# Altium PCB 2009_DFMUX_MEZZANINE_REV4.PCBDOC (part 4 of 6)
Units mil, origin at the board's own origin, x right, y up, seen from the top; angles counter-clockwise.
Board outline 4922.86 x 3627.76 mil, 6 copper layers (Top Layer, Internal Plane 1, Mid-Layer 1, Internal Plane 2, Mid-Layer 2, Bottom Layer); 519 components, 606 nets, 2175 pads, 757 vias.
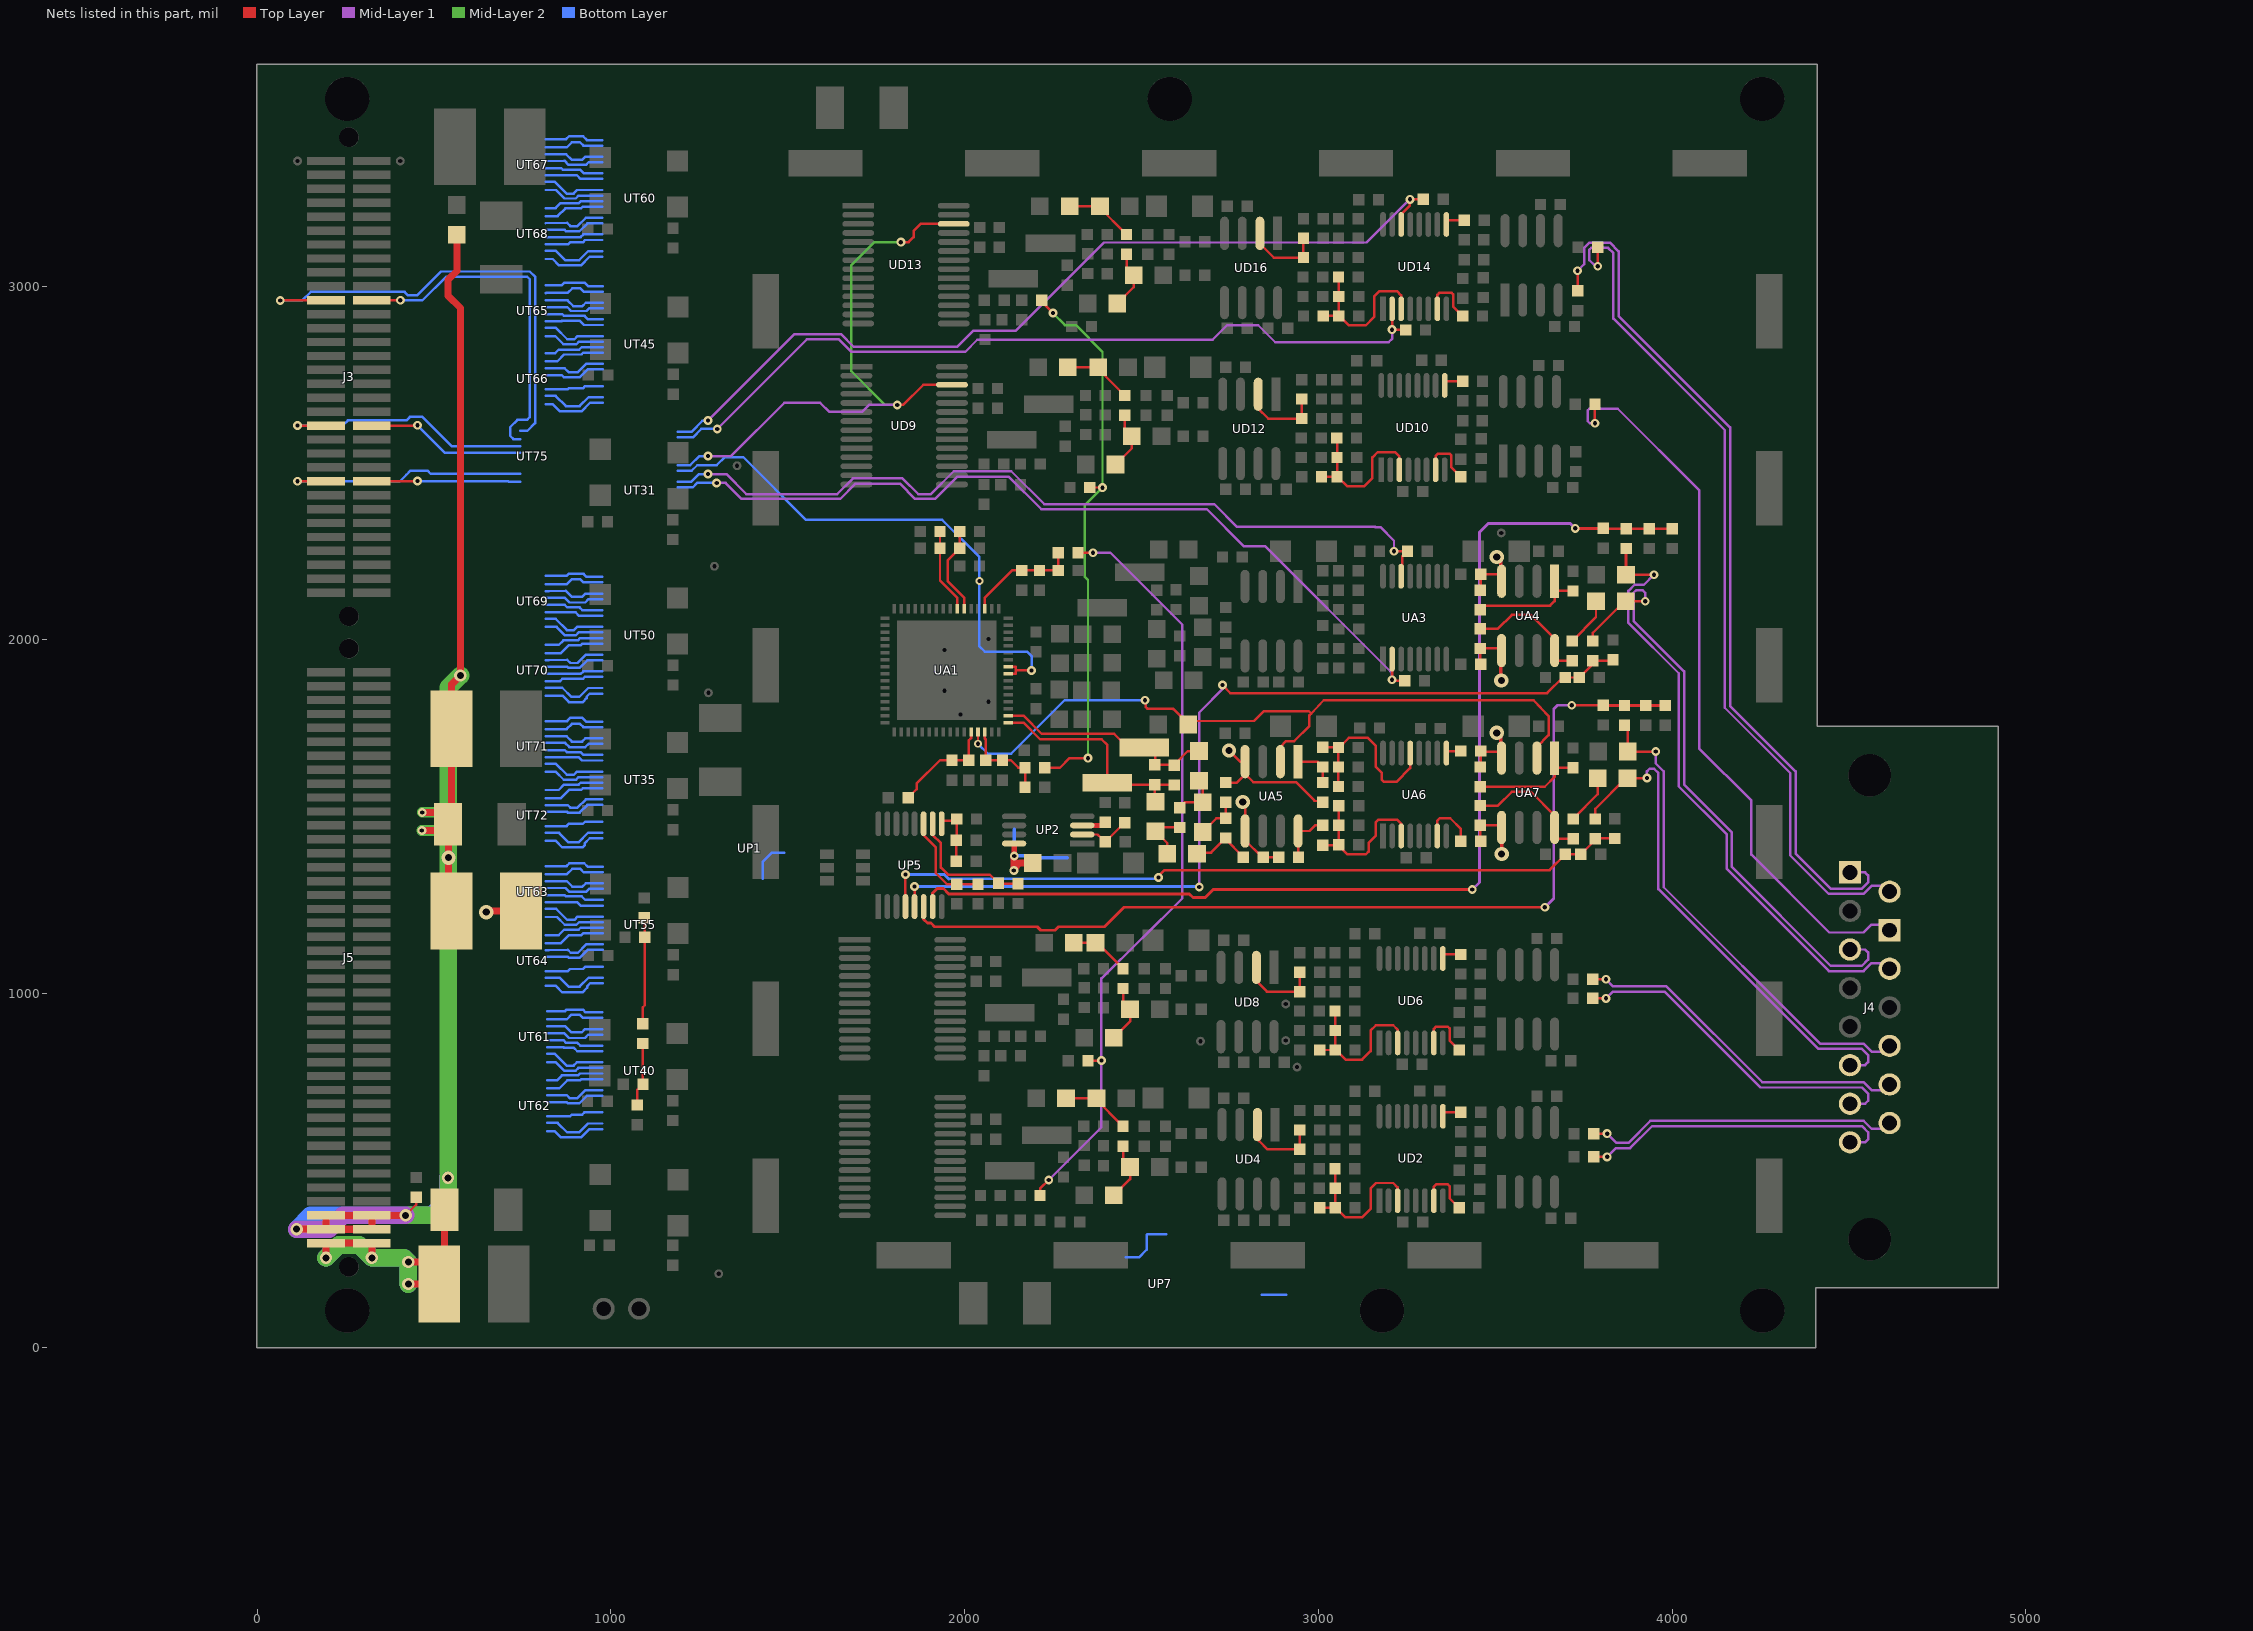
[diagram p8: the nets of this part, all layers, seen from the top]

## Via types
v1: diameter 25, hole 12, Top Layer to Bottom Layer, 692 vias
v2: diameter 40, hole 20, Top Layer to Bottom Layer, 39 vias
v3: diameter 35, hole 20, Top Layer to Bottom Layer, 23 vias
v4: diameter 22, hole 12, Top Layer to Bottom Layer, 3 vias

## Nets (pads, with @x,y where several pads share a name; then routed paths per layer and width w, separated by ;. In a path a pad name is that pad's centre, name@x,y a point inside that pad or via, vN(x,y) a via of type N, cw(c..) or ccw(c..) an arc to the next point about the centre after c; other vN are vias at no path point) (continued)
N196910: RP26.2 RP30.2 UP5.10 | length 370.5
  Top Layer w7: UP5.10@1909.48,1480.05 1909.48,1448.15 1932.63,1425 1932.63,1356.13 1952.63,1336 2071,1336 RP26.2@2095.63,1311.37 2096.63,1310.37 RP30.2@2150.63,1310.37
N197030: RD94.1 RD102.1 UD16.2 | length 223.7
  Top Layer w7: UD16.2@2834.63,3149 2842.63,3141 2842.63,3111.43 2873.63,3080.43 RD102.1@2957.63,3080.43 RD94.1@2957.63,3135.43
N197030_5448: RD64.1 RD72.1 UD12.2 | length 229.8
  Top Layer w7: UD12.2@2829.63,2694 2829.63,2654 2858.2,2625.43 RD72.1@2952.63,2625.43 RD64.1@2952.63,2680.43
N197030_5896: RD34.1 RD42.1 UD8.2 | length 229.2
  Top Layer w7: UD8.2@2824.63,1074 2824.63,1035 2854.2,1005.43 RD42.1@2947.63,1005.43 RD34.1@2947.63,1060.43
N197030_6344: RD4.1 RD12.1 UD4.2 | length 228.3
  Top Layer w7: UD4.2@2827.63,629.43 2832.63,624.43 2832.63,583 2856.2,559.43 RD12.1@2947.63,559.43 RD4.1@2947.63,614.43
N197797: RA5.2 RA6.2 UA1.23 | length 238.1
  Top Layer w7: RA6.2@1930.27,2305.87 RA5.2@1930.27,2258.37 1930.27,2167.37 1978.66,2118.97 UA1.23@1978.66,2087.85
N197910: CA2.1 RA7.2 RA8.2 RA9.1 UA1.19 | length 319.9
  Top Layer w7: UA1.19@2057.4,2087.85 2057.4,2119 2134.27,2195.87 CA2.1@2161.77,2195.87 RA8.2@2211.77,2195.87 RA9.1@2264.27,2195.87 RA7.2@2264.27,2245.87
N197956: RA3.2 RA4.2 UA1.22 | length 251.4
  Top Layer w7: RA4.2@1985.77,2305.87 RA3.2@1985.77,2258.37 1951.77,2224.37 1951.77,2165.87 1998.35,2119.29 UA1.22@1998.35,2087.85
N198124: CA31.1 RA43.2 RA44.1 RA49.2 UA1.62 | length 256
  Top Layer w7: UA1.62@2057.4,1739.43 2057.4,1720.23 2059.27,1718.37 CA31.1@2059.27,1659.37 RA43.2@2106.77,1659.37 2130.77,1659.37 2151.77,1638.37 RA49.2@2170.77,1638.37 RA44.1@2170.77,1583.37
N198251: CA33.2 RA54.1 RA56.2 UA1.60 | length 307.4
  Top Layer w7: RA56.2@1840.27,1553.37 1864.27,1577.37 1864.27,1593.37 1930.27,1659.37 RA54.1@1964.27,1659.37 CA33.2@2011.77,1659.37 2011.77,1715.87 2018.03,1722.13 UA1.60@2018.03,1739.43
N199059: CP4.1 UP1.3 | length 119.3
  Bottom Layer w7: CP4.1@1429.63,1324 1429.63,1373 1454.43,1397.8 UP1.3@1489.63,1397.8
N199942: CP18.1 RP25.1 RP27.1 RP29.2 UP5.5 | length 2623.4
  Top Layer w7: UP5.5@1858.33,1245.8 v1(1858.33,1302.33) ; v1(2728.63,1872) 2751.27,1849 3646.63,1849 3690.63,1893.37 RP25.1@3697.63,1893.37 RP29.2@3737.63,1893.37 3775.63,1931.37 RP27.1@3775.63,1940.37 3829.63,1940.37 CP18.1@3832.63,1943.37
  Mid-Layer 1 w7: v1(2663,1301) 2663,1794 2735,1866 v1(2728.63,1872)
  Bottom Layer w8: v1(1858.33,1302.33) 2661.67,1302.33 v1(2663,1301)
N199948: CP20.1 RP32.1 RP33.2 RP34.2 UP5.4 | length 2158.2
  Top Layer w7: UP5.4@1832.73,1245.8 v1(1832.73,1336.73) ; v1(2548,1328) 2544,1328 2565,1349 3653.27,1349 RP32.1@3697.63,1393.37 RP34.2@3741.63,1393.37 3782.63,1434.37 RP33.2@3782.63,1437.37 3783.63,1438.37 CP20.1@3837.63,1438.37
  Bottom Layer w7: 1955,1324 v1@2544,1324
  Bottom Layer w8: v1(1832.73,1336.73) 1942.27,1336.73 1955,1324 ; v1@2544,1324 v1(2548,1328)
N200349: CA35.2 UA1.61 UA5.2 UA7.2 | length 2139.8
  Top Layer w7: v4(2037.72,1705.87) UA1.61@2037.72,1739.43 ; v1(2510,1829) 2511.63,1829 2511.63,1810.37 2516.57,1805.43 2590,1805.43 2590,1804 2632.6,1761.4 CA35.2@2631.63,1760.43 2641.63,1770.43 2817.63,1770.43 2845.63,1798.43 2972.63,1798.43 2979.63,1791.43 ; UA5.2@2892.63,1655.43 2892.63,1697.43 2908.63,1713.43 2931.63,1713.43 2974.63,1756.43 2974.63,1786.43 2979.63,1791.43 ; UA7.2@3617.63,1665.43 3617.63,1697.43 3650.63,1730.43 3650.63,1784.43 3608.37,1829 3015,1829 2979.63,1791.43
  Mid-Layer 1 w7: v1(2510,1829) 2511.63,1829 v1@2511.63,1825.37
  Bottom Layer w7: v4(2037.72,1705.87) 2065.22,1678.37 2131.77,1678.37 2282.4,1829 v1(2510,1829)
N200703: CA29.2 JA2.2 LA7.1 RA41.1 UA1.1 | length 654.5
  Top Layer w7: UA1.1@2123.35,1766 2166.07,1766 2213.63,1718.43 2387.63,1718.43 2402.63,1703.43 JA2.2@2402.63,1595.43 2407.63,1590.43 RA41.1@2537.63,1590.43 ; LA7.1@2539.63,1542.43 2537.63,1544.43 RA41.1@2537.63,1590.43 ; CA29.2@2592.63,1589.43 2591.63,1590.43 RA41.1@2537.63,1590.43
N205033: CD13.2 LD3.2 LD4.1 | length 166.3
  Top Layer w7: LD3.2@2421.63,429.43 2467.63,475.43 LD4.1@2467.63,509.43 2447.63,529.43 CD13.2@2447.63,568.43
N205033_3007: CD73.2 LD15.2 LD16.1 | length 166.3
  Top Layer w7: LD15.2@2431.63,2950.43 2477.63,2996.43 LD16.1@2477.63,3030.43 2457.63,3050.43 CD73.2@2457.63,3089.43
N205033_5405: CD53.2 LD11.2 LD12.1 | length 166.3
  Top Layer w7: LD11.2@2426.63,2495.43 2472.63,2541.43 LD12.1@2472.63,2575.43 2452.63,2595.43 CD53.2@2452.63,2634.43
N205033_5853: CD33.2 LD7.2 LD8.1 | length 166.3
  Top Layer w7: LD7.2@2421.63,875.43 2467.63,921.43 LD8.1@2467.63,955.43 2447.63,975.43 CD33.2@2447.63,1014.43
N205049: CD13.1 LD1.2 LD2.1 | length 199.1
  Top Layer w7: LD1.2@2286.63,704.43 LD2.1@2367.63,704.43 ; LD2.1@2372.63,704.43 LD2.1@2367.63,704.43 ; CD13.1@2447.63,624.43 LD2.1@2367.63,704.43
N205049_2984: CD73.1 LD13.2 LD14.1 | length 199.1
  Top Layer w7: LD13.2@2296.63,3225.43 LD14.1@2377.63,3225.43 ; LD14.1@2382.63,3225.43 LD14.1@2377.63,3225.43 ; CD73.1@2457.63,3145.43 LD14.1@2377.63,3225.43
N205049_5379: CD53.1 LD9.2 LD10.1 | length 199.1
  Top Layer w7: LD9.2@2291.63,2770.43 LD10.1@2372.63,2770.43 ; LD10.1@2377.63,2770.43 LD10.1@2372.63,2770.43 ; CD53.1@2452.63,2690.43 LD10.1@2372.63,2770.43
N205049_5827: CD33.1 LD5.2 LD6.1 | length 169.8
  Top Layer w7: LD5.2@2308.63,1144 LD6.1@2369.63,1144 2374.63,1144 2447.63,1071 CD33.1@2447.63,1070.43
N205083: RD21.1 RD22.2 RD23.1 RD24.1 UD2.3 | length 458.8
  Top Layer w7: RD22.2@3003.63,394.43 RD23.1@3047.63,394.43 ; RD24.1@3046.63,504.43 3047.63,503.43 RD21.1@3047.63,449.43 RD23.1@3047.63,394.43 ; UD2.3@3223.83,414.43 3223.83,452.23 3211.63,464.43 3162.63,464.43 3147.63,449.43 3147.63,391.43 3123.63,367.43 3076.63,367.43 3049.63,394.43 RD23.1@3047.63,394.43
N205083_3003: RD111.1 RD112.2 RD113.1 RD114.1 UD14.3 | length 458.8
  Top Layer w7: RD112.2@3013.63,2915.43 RD113.1@3057.63,2915.43 ; RD114.1@3056.63,3025.43 3057.63,3024.43 RD111.1@3057.63,2970.43 RD113.1@3057.63,2915.43 ; UD14.3@3233.83,2935.43 3233.83,2973.23 3221.63,2985.43 3172.63,2985.43 3157.63,2970.43 3157.63,2912.43 3133.63,2888.43 3086.63,2888.43 3059.63,2915.43 RD113.1@3057.63,2915.43
N205083_5399: RD81.1 RD82.2 RD83.1 RD84.1 UD10.3 | length 458.8
  Top Layer w7: RD82.2@3008.63,2460.43 RD83.1@3052.63,2460.43 ; RD84.1@3051.63,2570.43 3052.63,2569.43 RD81.1@3052.63,2515.43 RD83.1@3052.63,2460.43 ; UD10.3@3228.83,2480.43 3228.83,2518.23 3216.63,2530.43 3167.63,2530.43 3152.63,2515.43 3152.63,2457.43 3128.63,2433.43 3081.63,2433.43 3054.63,2460.43 RD83.1@3052.63,2460.43
N205083_5847: RD51.1 RD52.2 RD53.1 RD54.1 UD6.3 | length 458.8
  Top Layer w7: RD52.2@3003.63,840.43 RD53.1@3047.63,840.43 ; RD54.1@3046.63,950.43 3047.63,949.43 RD51.1@3047.63,895.43 RD53.1@3047.63,840.43 ; UD6.3@3223.83,860.43 3223.83,898.23 3211.63,910.43 3162.63,910.43 3147.63,895.43 3147.63,837.43 3123.63,813.43 3076.63,813.43 3049.63,840.43 RD53.1@3047.63,840.43
N205093: RD3.1 UD2.9 | length 63.9
  Top Layer w7: UD2.9@3351.72,653.02 3351.72,654.43 3351.63,654.43 3351.63,665.43 3352.63,664.43 RD3.1@3402.63,664.43
N205093_2991: RD93.1 UD14.9 | length 63.9
  Top Layer w7: UD14.9@3361.72,3174.02 3361.72,3175.43 3361.63,3175.43 3361.63,3186.43 3362.63,3185.43 RD93.1@3412.63,3185.43
N205093_5387: RD63.1 UD10.9 | length 63.9
  Top Layer w7: UD10.9@3356.72,2719.02 3356.72,2720.43 3356.63,2720.43 3356.63,2731.43 3357.63,2730.43 RD63.1@3407.63,2730.43
N205093_5835: RD33.1 UD6.9 | length 63.9
  Top Layer w7: UD6.9@3351.72,1099.02 3351.72,1100.43 3351.63,1100.43 3351.63,1111.43 3352.63,1110.43 RD33.1@3402.63,1110.43
N205095: RD27.1 UD2.7 | length 160.9
  Top Layer w7: UD2.7@3326.23,414.43 3326.23,454.03 3332.63,460.43 3365.63,460.43 3370.63,455.43 3370.63,421.43 RD27.1@3397.63,394.43
N205095_2994: RD117.1 UD14.7 | length 160.9
  Top Layer w7: UD14.7@3336.23,2935.43 3336.23,2975.03 3342.63,2981.43 3375.63,2981.43 3380.63,2976.43 3380.63,2942.43 RD117.1@3407.63,2915.43
N205095_5389: RD87.1 UD10.7 | length 160.9
  Top Layer w7: UD10.7@3331.23,2480.43 3331.23,2520.03 3337.63,2526.43 3370.63,2526.43 3375.63,2521.43 3375.63,2487.43 RD87.1@3402.63,2460.43
N205095_5837: RD57.1 UD6.7 | length 160.9
  Top Layer w7: UD6.7@3326.23,860.43 3326.23,900.03 3332.63,906.43 3365.63,906.43 3370.63,901.43 3370.63,867.43 RD57.1@3397.63,840.43
N238970: RA17.2 RA18.1 UA4.4 | length 235.6
  Top Layer w7: RA18.1@3457.63,2140.43 3458.63,2141.43 RA17.2@3458.63,2185.43 3512.63,2185.43 3515,2183.07 3517.63,2180.43 UA4.4@3517.63,2165.43
  Top Layer w10: v2(3504,2234) v2@3515,2223 ; UA4.4@3517.63,2165.43 3515,2168.07 UA4.4@3515,2183.07 ; UA4.4@3515,2183.07 v2@3515,2223 ; UA4.4@3515,2183.07 v2@3515,2223
N238974: RA13.1 RA18.2 UA4.1 | length 328.4
  Top Layer w7: RA18.2@3457.63,2084.43 3469.63,2096.43 3654.63,2096.43 3667.63,2109.43 UA4.1@3667.63,2138 ; UA4.1@3667.63,2165.43 UA4.1@3667.63,2138 ; RA13.1@3719.63,2138 UA4.1@3667.63,2138
N238978: RA28.2 RA29.1 UA4.8 | length 365.2
  Top Layer w7: RA28.2@3457.63,2031.43 3507.63,2031.43 3546.63,2070.43 3600.63,2070.43 3667.63,2003.43 UA4.8@3667.63,1969.43 3667.63,1943.37 3670.57,1940.43 RA29.1@3717.63,1940.43
N238986: RA27.2 RA28.1 UA4.5 | length 193.5
  Top Layer w7: RA27.2@3458.63,1930.43 3457.63,1931.43 RA28.1@3457.63,1975.43 3511.63,1975.43 UA4.5@3517.63,1969.43
  Top Layer w10: v2(3517,1885) 3516,1886 3516,1968 3517.43,1969.43 UA4.5@3517.63,1969.43
N244377: RP28.2 RP31.2 UP5.11 | length 286.1
  Top Layer w7: UP5.11@1883.88,1480.05 1883.88,1448.12 1918.63,1413.37 1918.63,1340 1949.27,1309.37 RP31.2@1977.63,1309.37 RP28.2@2037.63,1309.37
N245845: CA47.1 RA29.2 | length 140.3
  Top Layer w7: RA29.2@3717.63,1996.43 3717.63,1997 3784.63,2064 CA47.1@3784.63,2109
N247609: RP21.2 RP22.2 RP23.1 UP5.9 | length 170.6
  Top Layer w7: UP5.9@1935.07,1480.05 1935.07,1484.62 1939.85,1489 1973.63,1489 1977.63,1493 RP23.1@1977.63,1493.37 1977.63,1434.37 RP22.2@1976.63,1433.37 RP21.2@1976.63,1374
N247828: RA45.1 RA47.2 RA48.1 RA50.1 UA6.3 | length 460.9
  Top Layer w7: RA47.2@3012.63,1419.43 3056.63,1419.43 RA50.1@3057.63,1420.43 ; RA48.1@3057.63,1530.43 RA45.1@3057.63,1475.43 RA50.1@3057.63,1420.43 ; UA6.3@3233.83,1445.43 3233.83,1480.23 3222.63,1491.43 3169.63,1491.43 3161.63,1483.43 3161.63,1445.43 3141.63,1425.43 3141.63,1401.43 3133.63,1393.43 3081.63,1393.43 3057.63,1417.43 RA50.1@3057.63,1420.43
N247840: RA34.1 UA6.9 | length 43.2
  Top Layer w7: UA6.9@3361.77,1679.68 3367.52,1685.43 RA34.1@3402.63,1685.43
N247844: RA51.1 UA6.7 | length 160.1
  Top Layer w7: UA6.7@3336.23,1445.43 3336.23,1489.03 3342.63,1495.43 3372.63,1495.43 3402.63,1465.43 RA51.1@3402.63,1430.43
N247852: RA33.2 RA37.2 RA38.2 RA39.2 UA6.13 | length 524.2
  Top Layer w7: RA33.2@3012.63,1696.43 3055.63,1696.43 RA37.2@3056.63,1695.43 RA37.2@3057.63,1694.43 ; RA39.2@3056.63,1585.43 RA38.2@3056.63,1640.43 3056.63,1693.43 RA37.2@3057.63,1694.43 ; UA6.13@3259.4,1679.68 3259.4,1637.2 3220.63,1598.43 3185.63,1598.43 3178.63,1605.43 3178.63,1624.43 3162.63,1640.43 3162.63,1699.43 3139.63,1722.43 3085.63,1722.43 RA37.2@3057.63,1694.43
N247880: RA32.1 RA40.2 UA5.4 | length 410.8
  Top Layer w7: RA40.2@2737.63,1596.43 2769.63,1596.43 2792.63,1619.43 UA5.4@2792.63,1620.43 ; v2(2747,1687) 2778.57,1655.43 UA5.4@2792.63,1655.43 UA5.4@2792.63,1620.43 ; RA32.1@3012.63,1540.43 2988.63,1545.43 2936.63,1597.43 2815.63,1597.43 UA5.4@2792.63,1620.43
N247884: RA32.2 RA33.1 UA5.1 | length 120.2
  Top Layer w7: UA5.1@2942.63,1655.43 2997.63,1655.43 RA33.1@3012.63,1640.43 RA32.2@3012.63,1596.43
N247888: RA46.2 RA47.1 UA5.8 | length 151
  Top Layer w7: RA46.2@2943.63,1385.43 2942.63,1386.43 UA5.8@2942.63,1459.43 2974.63,1459.43 2990.63,1475.43 RA47.1@3012.63,1475.43
N247896: RA42.2 RA46.1 UA5.5 | length 225.2
  Top Layer w7: v2(2786,1541) 2792.63,1534.37 UA5.5@2792.63,1459.43 2792.63,1433.43 2840.63,1385.43 RA42.2@2843.63,1385.43 RA46.1@2887.63,1385.43
N247928: CA29.1 JA2.1 LA5.1 RA41.2 UA1.2 | length 635.3
  Top Layer w7: UA1.2@2123.35,1785.69 2166.37,1785.7 2217.63,1734.43 2422.63,1734.43 2461.63,1695.43 JA2.1@2507.63,1695.43 2521.63,1695.43 2538.63,1678.43 2538.63,1647.43 RA41.2@2537.63,1646.43 2591.63,1646.43 CA29.1@2592.63,1645.43 2592.63,1647.43 2630.63,1685.43 LA5.1@2662.63,1685.43
N247964: RA34.2 RA35.1 UA7.4 | length 196.3
  Top Layer w7: RA35.1@3457.63,1640.43 3458.63,1641.43 RA34.2@3458.63,1685.43 3460.07,1684 3510,1684 3515,1679 3517.63,1676.37 UA7.4@3517.63,1665.43
  Top Layer w10: v2(3504,1737) 3515,1726 3515,1679 3515,1668.07 UA7.4@3517.63,1665.43
N247968: RA35.2 RA36.1 UA7.1 | length 327.8
  Top Layer w7: RA35.2@3457.63,1584.43 3639.63,1584.43 3667.63,1612.43 3667.63,1635 UA7.1@3670.63,1638 ; UA7.1@3667.63,1665.43 3667.63,1638 UA7.1@3670.63,1638 ; RA36.1@3719.63,1638 UA7.1@3670.63,1638
N247972: RA52.2 RA53.1 UA7.8 | length 365.9
  Top Layer w7: RA52.2@3457.63,1531.43 3507.63,1531.43 3546.63,1570.43 3600.63,1570.43 3667.63,1503.43 UA7.8@3667.63,1469.43 3667.63,1449.37 3679.57,1437.43 RA53.1@3720.63,1437.43
N247980: RA51.2 RA52.1 UA7.5 | length 183.5
  Top Layer w7: RA51.2@3458.63,1430.43 3457.63,1431.43 RA52.1@3457.63,1475.43 3511.63,1475.43 UA7.5@3517.63,1469.43
  Top Layer w10: UA7.5@3517.63,1469.43 3518,1469.07 v2(3518,1394)
N248164: CA30.1 LA6.2 RA40.1 | length 126.2
  Top Layer w7: LA6.2@2672.63,1456.43 2711.63,1495.43 CA30.1@2737.63,1495.43 RA40.1@2737.63,1540.43
N248168: CA30.2 LA8.2 RA42.1 | length 173.9
  Top Layer w7: LA8.2@2656.63,1395.43 2659.63,1398.43 2696.63,1398.43 CA30.2@2737.63,1439.43 2737.63,1436.43 2787.63,1386.43 RA42.1@2787.63,1385.43
N248172: CA28.1 LA5.2 LA6.1 | length 136.4
  Top Layer w7: CA28.1@2607.63,1525.43 2622.63,1540.43 LA6.1@2672.63,1540.43 2672.63,1591.43 LA5.2@2662.63,1601.43
N248196: CA28.2 LA7.2 LA8.1 | length 149.2
  Top Layer w7: LA8.1@2572.63,1395.43 2572.63,1425.43 LA7.2@2539.63,1458.43 2550.63,1469.43 CA28.2@2607.63,1469.43
N248744: CA49.1 RA53.2 | length 144.1
  Top Layer w7: RA53.2@3720.63,1493.43 3720.63,1495 3789.63,1564 CA49.1@3789.63,1609
N536527: CA47.2 J4.3 RP27.2 | length 1743.7
  Top Layer w7: RP27.2@3775.63,1996.37 3775.63,2020 3864.63,2109 CA47.2@3868.63,2109 v1(3923.63,2109)
  Mid-Layer 1 w7: v1(3923.63,2109) 3923.63,2132.93 3916.13,2140.43 3898.63,2140.43 3891.13,2132.93 3891.13,2052.93 4033.63,1910.43 4033.63,1590.43 4168.63,1455.43 4168.63,1357.93 4448,1078.57 4536.13,1078.57 4553.63,1096.07 4553.63,1116.07 4545.2,1124.5 J4.3@4502.5,1124.5
N536537: CA46.1 J4.11 RP56.2 | length 1741.4
  Top Layer w7: CA46.1@3869.63,2184 v1(3948.63,2184)
  Top Layer w8: CA46.1@3869.63,2184 3869.63,2257.63 RP56.2@3870,2258
  Mid-Layer 1 w7: v1(3948.63,2184) 3920.07,2155.43 3893.63,2155.43 3876.13,2137.93 3876.13,2047.93 4018.63,1905.43 4018.63,1585.43 4153.63,1450.43 4153.63,1352.93 4443,1063.57 4541.13,1063.57 4563.63,1086.07 4598.43,1086.07 J4.11@4614.5,1070
N536553: CA48.1 J4.13 RP59.2 | length 1387.3
  Top Layer w7: RP59.2@3865,1758 3874.63,1748.37 CA48.1@3874.63,1684 v1(3953.63,1684)
  Mid-Layer 1 w7: v1(3953.63,1684) 3953.63,1650.43 3976.13,1627.93 3976.13,1300.43 4418.13,858.43 4541.13,858.43 4563.63,835.93 4598.43,835.93 J4.13@4614.5,852
N536575: CA49.2 J4.6 RP33.1 | length 1455.6
  Top Layer w7: RP33.1@3782.57,1493.43 RP33.1@3782.63,1493.37 3782.63,1522 CA49.2@3869.63,1609 ; CA49.2@3873.63,1609 v1(3928.63,1609)
  Mid-Layer 1 w7: v1(3928.63,1609) 3928.63,1627.93 3936.13,1635.43 3948.63,1635.43 3961.13,1622.93 3961.13,1295.43 4413.13,843.43 4536.13,843.43 4553.63,825.93 4553.63,805.93 4545.2,797.5 J4.6@4502.5,797.5
N536618: J4.14 RD43.2 | length 975.4
  Top Layer w7: RD43.2@3775.63,1040.37 v1(3813.13,1040.37)
  Mid-Layer 1 w7: v1(3813.13,1040.37) 3833.07,1020.43 3983.63,1020.43 4254.63,749.43 4541.13,749.43 4563.63,726.93 4598.43,726.93 J4.14@4614.5,743
N536666: J4.7 RD48.2 | length 980
  Top Layer w7: RD48.2@3775.63,986.37 v1(3813.13,986.37)
  Mid-Layer 1 w7: v1(3813.13,986.37) 3832.2,1005.43 3978.63,1005.43 4249.63,734.43 4536.13,734.43 4553.63,716.93 4553.63,696.93 4545.2,688.5 J4.7@4502.5,688.5
N538961: J4.15 RD13.2 | length 888.5
  Top Layer w7: RD13.2@3778.63,604 v1(3816.13,604)
  Mid-Layer 1 w7: v1(3816.13,604) 3842.2,577.93 3876.13,577.93 3938.63,640.43 4541.13,640.43 4563.63,617.93 4598.43,617.93 J4.15@4614.5,634
N539025: J4.8 RD18.2 | length 892.9
  Top Layer w7: RD18.2@3778.63,538.37 v1(3816.13,538.37)
  Mid-Layer 1 w7: v1(3816.13,538.37) 3840.7,562.93 3881.13,562.93 3943.63,625.43 4536.13,625.43 4553.63,607.93 4553.63,587.93 4545.2,579.5 J4.8@4502.5,579.5
N539569: J4.10 RD73.2 | length 2108.5
  Top Layer w7: v1(3781.63,2612) RD73.2@3781.63,2666
  Mid-Layer 1 w7: v1(3781.63,2612) 3767.07,2612 3761.13,2617.93 3761.13,2647.93 3766.13,2652.93 3846.13,2652.93 4076.13,2422.93 4076.13,1692.93 4223.63,1545.43 4223.63,1392.93 4444,1172.57 4541.13,1172.57 4563.63,1195.07 4598.43,1195.07 J4.10@4614.5,1179
N539716: J4.1 RD108.2 | length 2480.7
  Top Layer w7: RD108.2@3732.63,2986.43 v1(3732.63,3042.93)
  Mid-Layer 1 w7: v1(3732.63,3042.93) 3751.13,3061.43 3751.13,3107.93 3766.13,3122.93 3823.63,3122.93 3848.63,3097.93 3848.63,2915.43 4163.63,2600.43 4163.63,1812.93 4348.63,1627.93 4348.63,1395.43 4447.5,1296.57 4536.13,1296.57 4553.63,1314.07 4553.63,1334.07 4545.2,1342.5 J4.1@4502.5,1342.5
N539798: J4.9 RD103.2 | length 2441.8
  Top Layer w7: v1(3789.63,3056) RD103.2@3789.63,3110
  Mid-Layer 1 w7: v1(3789.63,3056) 3783.07,3056 3766.13,3072.93 3766.13,3102.93 3771.13,3107.93 3818.63,3107.93 3833.63,3092.93 3833.63,2907.93 4148.63,2592.93 4148.63,1807.93 4333.63,1622.93 4333.63,1390.43 4442.5,1281.57 4541.13,1281.57 4563.63,1304.07 4598.43,1304.07 J4.9@4614.5,1288
N562193: RA30.2 UA3.2 UT31.12 | length 2470.3
  Top Layer w7: UA3.2@3208.23,1945.43 3206.63,1943.83 3206.63,1934.43 3208.63,1932.43 3208.63,1894 3199.63,1885 3207.63,1885 v1(3207.63,1887) 3210.63,1884 RA30.2@3243.63,1884
  Mid-Layer 1 w7: v1(1299,2443.37) 1324.27,2443.37 1369.63,2398 1648.36,2398 1691.77,2441.41 1816.77,2441.41 1860.18,2398 1915.86,2398 1979.27,2461.41 2124.27,2461.41 2216.68,2369 2685,2369 2790,2264 2850,2264 3203,1911 3207.63,1911 v1(3207.63,1887)
  Bottom Layer w7: UT31.12@1188.63,2430.67 1231.5,2430.67 1243.8,2443.37 v1(1299,2443.37)
N562649: RA10.2 UA3.14 UT31.11 | length 2348
  Top Layer w7: v1(3213.63,2250.43) RA10.2@3251.63,2250.43 3236.63,2235.43 3236.63,2182.5 UA3.14@3233.82,2179.68
  Mid-Layer 1 w7: v1(1274.27,2468.37) 1326.27,2468.37 1382.63,2412 1639.86,2412 1684.27,2456.41 1824.27,2456.41 1868.68,2412 1904.86,2412 1969.27,2476.41 2131.77,2476.41 2225.18,2383 2706,2383 2770,2319 3160,2319 3160.37,2318.63 3175,2318.63 3213.63,2280 v1(3213.63,2250.43)
  Bottom Layer w7: UT31.11@1188.63,2446.37 1227,2446.37 1249,2468.37 v1(1274.27,2468.37)
N563114: RA1.1 UA1.8 UA1.9 UT31.9 | length 1546
  Top Layer w7: UA1.8@2122.63,1903.9 UA1.8@2123.35,1903.9 ; UA1.9@2122.63,1923.6 UA1.9@2123.35,1923.6 ; UA1.8@2123.35,1903.8 2144.27,1903.8 2144.27,1923.48 UA1.9@2123.35,1923.48 ; 2144.27,1913.37 v1(2189.27,1913.37)
  Bottom Layer w7: UT31.9@1188.63,2477.77 1228.4,2477.77 1244,2493.37 1299,2493.37 1322.04,2516.41 1374.27,2516.41 1551.77,2338.91 1936.77,2338.91 2041.77,2233.91 RA1.1@2041.77,2208.37 v4(2041.77,2165.87) 2041.77,1981.41 2056.77,1966.41 2176.77,1966.41 2189.27,1953.91 v1(2189.27,1913.37)
N563431: UD9.26 UD13.26 UT31.8 | length 1708.6
  Top Layer w7: v1(1809.63,2664) 1826.27,2664 1882.9,2720.63 UD9.26@1964.03,2720.63 ; v1(1819.63,3124) 1841.63,3124 1855.63,3138 1855.63,3156 1875.27,3175.63 UD13.26@1969.03,3175.63
  Mid-Layer 1 w7: v1(1274.27,2519.37) 1340,2519.37 1490.63,2670 1591.63,2670 1617.63,2644 1709.63,2644 1729.63,2664 v1(1809.63,2664)
  Mid-Layer 2 w7: v1(1809.63,2664) 1774.63,2664 1679.63,2759 1679.63,3059 1744.63,3124 v1(1819.63,3124)
  Bottom Layer w7: UT31.8@1188.63,2493.47 1224.1,2493.47 1250,2519.37 v1(1274.27,2519.37)
N564745: RD119.2 UD14.2 UT31.3 | length 2328.2
  Top Layer w7: UD14.2@3208.23,2935.43 v1(3208.23,2876.6) 3246.47,2876.6 3246.63,2876.43 RD119.2@3246.63,2875.43
  Mid-Layer 1 w7: v1(1300.63,2596) 1553.63,2849 1644.63,2849 1679.63,2814 2001.63,2814 2035.63,2848 2701,2848 2742,2889 2830,2889 2878,2841 3198.63,2841 3208.23,2850.6 v1(3208.23,2876.6)
  Bottom Layer w7: UT31.3@1188.63,2571.97 1231.88,2571.97 1255.52,2596 v1(1300.63,2596)
N565087: RD91.2 UD14.14 UT31.2 | length 2496
  Top Layer w7: UD14.14@3233.8,3174.02 3231.63,3176.18 3231.63,3200.43 3258.63,3227.43 v1@3258.63,3245.43 ; v1(3258.63,3245) v1@3258.63,3245.43 ; RD91.2@3296.63,3245.43 v1@3258.63,3245.43
  Mid-Layer 1 w7: v1(1274.63,2620) 1518.63,2864 1650.63,2864 1686.63,2828 1978.63,2828 2023.63,2873 2144,2873 2394,3123 3135.63,3123 3257.63,3245 v1(3258.63,3245)
  Bottom Layer w7: UT31.2@1188.63,2587.67 1227.3,2587.67 1258.63,2619 1275.63,2619 v1(1274.63,2620)
N565612: J3.48 UT75.9 | length 420.9
  Top Layer w7: J3.48@324.55,2448 452.87,2448 v1(453.63,2448.77)
  Bottom Layer w7: v1(453.63,2448.77) 709.63,2448.77 712.03,2446.37 UT75.9@744.13,2446.37
N566158: J3.47 UT75.10 | length 807.7
  Top Layer w7: v1@113.63,2447 115,2448 194.63,2448 v1(114.33,2448)
  Bottom Layer w7: v1(114.33,2448) 403.55,2448 422.05,2466.37 ; 422.07,2466.37 433.93,2478.37 481.63,2478.37 490.63,2469.37 UT75.10@744.13,2469.37
N570816: CP9.1 CP23.1 CP24.1 LP2.2 RP11.1 UP2.8 | length 643.9
  Top Layer w7: v2(647.63,1230) v2@651,1233.37 ; UP2.8@2139.73,1424 2139.73,1388.1 2140.63,1389 v1(2140,1389)
  Top Layer w10: UP2.8@2139.73,1424 UP2.8@2140,1423.73
  Top Layer w15: v1@2140,1389 UP2.8@2140,1423.73
  Top Layer w20: v2@651,1233.37 LP2.2@746.3,1233.37 ; v1(2140,1389) 2140,1354 2155,1369 RP11.1@2192.63,1369
  Bottom Layer w7: 2200,1389 CP9.1@2205,1384
  Bottom Layer w10: 2200,1389 v1(2140,1389) ; CP9.1@2205,1384 CP24.1@2290,1384 ; v1(2140,1389) CP23.1@2140,1464 ; v1(2140,1389) CP23.1@2140,1464 ; v1(2140,1389) CP23.1@2140,1464
  other v1: 2139,1348
N570824: CP8.1 UP2.3 | length 68.6
  Top Layer w7: CP8.1@2388.83,1475.2 CP8.1@2397.63,1484
  Top Layer w15: UP2.3@2332.63,1475.2 CP8.1@2388.83,1475.2
N570828: RP9.2 RP10.1 UP2.2 | length 154.5
  Top Layer w7: UP2.2@2332.63,1449.6 2376.03,1449.6 2386.63,1439 2397.63,1439 RP10.1@2403.13,1433.5 ; RP10.1@2397.63,1429 2398.63,1429 RP10.1@2403.13,1433.5 ; RP9.2@2452.63,1483 RP10.1@2403.13,1433.5
N570972: J3.40 UT75.13 | length 452.2
  Top Layer w7: J3.40@324.55,2605.47 452.87,2605.47 v1(453.63,2606.23)
  Bottom Layer w7: v1(453.63,2606.23) 453.77,2606.23 531.63,2528.37 UT75.13@744.13,2528.37
N571170: J3.39 UT75.14 | length 754.5
  Top Layer w7: v1(114.33,2605.47) J3.39@194.63,2605.47
  Bottom Layer w7: v1(114.33,2605.47) 241.73,2605.47 256.63,2620.37 422.03,2620.37 431.63,2629.97 467.03,2629.97 549.63,2547.37 UT75.14@744.13,2547.37
N582215: J3.22 UT75.15 | length 989.9
  Top Layer w7: J3.22@324.55,2959.77 v1(404.85,2959.77)
  Bottom Layer w7: v1(404.85,2959.77) 467.4,2959.77 534,3026 763.63,3026 770.63,3019.37 770.63,2629.37 762.63,2621.37 735.63,2621.37 715.63,2601.37 715.63,2576.37 724.63,2567.37 UT75.15@744.13,2567.37
N582703: J3.21 UT75.16 | length 1363.4
  Top Layer w7: v1@64.23,2959.77 v1@66.32,2959.77 ; v1(65.55,2959) v1@66.32,2959.77 ; J3.21@194.63,2959.77 v1@66.32,2959.77
  Bottom Layer w7: v1(65.55,2959) 127.27,2959 151.7,2983.43 416.63,2983.43 425.63,2974.43 453.07,2974.43 520,3041 770.63,3041 785.63,3026.37 785.63,2612.37 763.63,2590.37 UT75.16@744.13,2590.37
N609644: CP1.2 RP1.2 RP2.1 | length 181
  Top Layer w7: RP1.2@1074.63,685 1074.63,728 CP1.2@1090.63,744 1090.63,858 RP2.1@1089.63,859
N609835: CP2.2 RP2.2 RP3.1 | length 301.9
  Top Layer w7: RP2.2@1089.63,915 1089.63,961 1095.63,967 CP2.2@1095.63,1159 1095.63,1213 RP3.1@1094.63,1214
N611462: RA7.1 RD20.2 RD60.2 | length 2197.6
  Top Layer w7: RD20.2@2213.13,429 2213.13,448.5 v1(2237.63,473) ; RA7.1@2320.27,2245.87 v1(2362.77,2245.87) ; RD60.2@2348.63,810.43 v1(2386.57,810.43)
  Mid-Layer 1 w7: v1(2237.63,473) 2386.57,621.93 v1(2386.57,810.43) 2386.57,1042.93 2615,1269 2615,2042.64 2411.77,2245.87 v1(2362.77,2245.87)
N612269: RA49.1 RD90.2 RD110.2 | length 1578.9
  Top Layer w7: RD110.2@2217.63,2960 2217.63,2956 v1(2249.63,2924) ; RA49.1@2226.77,1638.37 2269.27,1638.37 2296.27,1665.37 v1(2348.63,1665.37) ; RD90.2@2353.63,2430.43 2390.07,2430.43 v1(2389.63,2430)
  Mid-Layer 2 w7: v1(2249.63,2924) 2249.57,2923.93 2249.57,2923.07 2283.2,2889.43 2314.2,2889.43 2389.63,2814 v1(2389.63,2430) 2339.27,2379.64 2339.27,2178.37 2348.63,2169 v1(2348.63,1665.37)
N617296: CP5.1 J5.79 J5.80 J5.81 J5.82 LP1.1 LP2.1 RP4.2 RP13.2 | length 5781.1
  Top Layer w7: J5.80@324.55,373.07 324.62,373 v3@416.63,373 ; v3@416.7,373.07 v3@416.63,373 ; RP4.2@449.63,424 449.63,403 v3(419.63,373) v3@416.63,373 ; CP5.1@523.63,1444.73 539.63,1460.73 CP5.1@539.63,1478.37 ; CP5.1@523.63,1512 539.63,1496 CP5.1@539.63,1478.37 ; LP2.1@540.63,1242.37 LP2.1@549.63,1233.37 ; CP5.1@540.63,1477.37 CP5.1@539.63,1478.37 ; LP1.1@547.63,1796 549.63,1798 LP1.1@549.63,1748.37 ; CP5.1@549.63,1488 540,1478.37 CP5.1@539.63,1478.37 ; CP5.1@539.63,1478 CP5.1@539.63,1478.37 ; CP5.1@539.63,1478 522.63,1461 CP5.1@539.63,1478
  Top Layer w20: v3(111.63,334) 194.33,334 J5.81@194.63,333.7 ; v1(466.63,1512) CP5.1@523.63,1512 ; LP2.1@540.63,1242.37 v2(540.63,1384) CP5.1@540.63,1477.37 ; CP5.1@549.63,1488 LP1.1@549.63,1748.37 550,1748.73 550,1798.37 550,1874.37 ; RP13.2@564.63,3145 564.63,3042.13 540,3017.5 540,2972.5 574.63,2937.87 v3(574.63,1899) ; J5.81@194.63,333.7 J5.79@194.63,373.07 ; J5.81@194.63,333.7 J5.82@324.55,333.7 J5.80@324.55,373.07 ; J5.81@194.63,333.7 J5.79@194.63,373.07 ; J5.79@194.63,373.07 J5.80@324.55,373.07 ; J5.80@324.55,373.07 416.7,373.07 J5.80@324.55,373.07 ; 550,1874.37 v3(574.63,1899) ; 550,1874.37 v3(574.63,1899) ; v1(465.63,1461) 522.63,1461 v1(465.63,1461)
  Mid-Layer 1 w50: v3(111.63,334) 204,334 243,373 v3(419.63,373)
  Mid-Layer 2 w30: v1(465.63,1461) 539.13,1461 ; v1(466.63,1512) 538.63,1512
  Mid-Layer 2 w50: v3(419.63,373) 508,373 540.63,405.63 v2(540.63,1384) 540.63,1865 v3(574.63,1899)
  Bottom Layer w50: v3(111.63,334) 150.63,373 v3(419.63,373) 493.63,373 539.63,419 v3(539.63,479)
N617312: CP17.2 J5.83 J5.84 LP4.1 | length 1427.3
  Top Layer w7: LP4.1@513.63,241 LP4.1@514.63,240 ; LP4.1@529.63,194 LP4.1@514.63,179 ; LP4.1@514.63,179 LP4.1@514.63,240 ; LP4.1@514.63,179 LP4.1@514.63,240
  Top Layer w20: v3(194.63,252.92) J5.83@194.63,294.33 J5.84@324.55,294.33 ; v3(427.63,179) LP4.1@514.63,179 ; v3(427.63,241) LP4.1@513.63,241 ; LP4.1@529.63,194 CP17.2@529.63,389 ; J5.84@324.55,294.33 v3(324.55,252.92) J5.84@324.55,294.33
  Mid-Layer 2 w50: v3(194.63,252.92) 230.72,289 288.47,289 v3(324.55,252.92) 415.72,252.92 v3(427.63,241) v3(427.63,179)
  Bottom Layer w50: v3(194.63,252.92) 231.72,290 287.47,290 v3(324.55,252.92) 415.72,252.92 v3(427.63,241) v3(427.63,179)
N714404: DP4.1 RP19.1 | length 70
  Bottom Layer w7: DP4.1@2839.63,149 RP19.1@2909.63,149
N717936: RP20.1 RP24.2 UP7.4 | length 166.5
  Bottom Layer w7: UP7.4@2454.63,254 2492.63,254 2514.63,276 RP20.1@2514.63,318 2515.63,319 RP24.2@2569.63,319
N794655: CP45.1 RP54.1 RP55.2 RP56.1 UP5.7 | length 3168.1
  Top Layer w8: UP5.7@1909.53,1245.8 1909.53,1283.53 1922.5,1296.5 1940,1296.5 1955,1281.5 2635,1281.5 2645,1271.5 2680,1271.5 2702.5,1294 v1(3435,1294) ; v1(3726,2315) RP55.2@3805,2315 3806,2314 RP56.1@3870,2314 RP54.1@3935,2314 CP45.1@4000,2314
  Mid-Layer 1 w8: v1(3435,1294) 3455,1314 3455,2304 3480,2329 3712,2329 v1(3726,2315)
N795104: CP46.1 RP57.1 RP58.2 RP59.1 UP5.6 | length 2721.9
  Top Layer w8: UP5.6@1883.93,1245.8 1883.93,1210.07 1895,1199 1905,1199 1915,1189 2205,1189 2215,1179 2255,1179 2265,1189 2395,1189 2450,1244 v1(3640,1244) ; v1(3716,1815) RP58.2@3805,1815 3806,1814 RP59.1@3865,1814 RP57.1@3925,1814 CP46.1@3980,1814
  Mid-Layer 1 w8: v1(3640,1244) 3665,1269 3665,1804 3676,1815 v1(3716,1815)
N839929: UT50.29 UT70.6 | length 165.9
  Bottom Layer w7: UT70.6@815.13,1883.37 856.63,1883.37 862.63,1889.37 920.83,1889.37 926.13,1895.07 UT50.29@976.03,1895.07
N839929_9383: UT60.29 UT68.6 | length 165.7
  Bottom Layer w7: UT68.6@815.13,3118.37 879.63,3118.37 884.63,3123.37 920.63,3123.37 927.33,3130.07 UT60.29@976.03,3130.07
N839929_10469: UT45.29 UT66.6 | length 165.5
  Bottom Layer w7: UT66.6@815.13,2708.37 878.63,2708.37 880.63,2710.37 920.63,2710.37 927.33,2717.07 UT45.29@977.03,2717.07
N839929_10665: UT55.29 UT64.6 | length 167.2
  Bottom Layer w7: UT64.6@815.13,1063.37 878.63,1063.37 884.63,1069.37 921.63,1069.37 928.33,1076.07 UT55.29@977.03,1076.07
N839929_10861: UT40.29 UT62.6 | length 159.3
  Bottom Layer w7: UT62.6@820.13,653.37 884.63,653.37 888.63,657.37 918.63,657.37 925.33,664.07 UT40.29@975.03,664.07
N839929_11253: UT35.29 UT72.6 | length 166.1
  Bottom Layer w7: UT72.6@815.13,1473.37 874.63,1473.37 880.63,1479.37 920.63,1479.37 927.63,1486.07 UT35.29@976.03,1486.07
N839997: UT50.27 UT70.7 | length 182.1
  Bottom Layer w7: UT70.7@815.13,1864.37 862.63,1864.37 888.63,1838.37 910.63,1838.37 935.93,1863.67 UT50.27@976.03,1863.67
N839997_9355: UT60.27 UT68.7 | length 182.1
  Bottom Layer w7: UT68.7@815.13,3099.37 844.63,3099.37 870.63,3073.37 910.63,3073.37 935.93,3098.67 UT60.27@976.03,3098.67
N839997_10465: UT45.27 UT66.7 | length 184.4
  Bottom Layer w7: UT66.7@815.13,2689.37 843.63,2689.37 872.63,2660.37 911.63,2660.37 936.93,2685.67 UT45.27@977.03,2685.67
N839997_10661: UT55.27 UT64.7 | length 182.7
  Bottom Layer w7: UT64.7@815.13,1044.37 855.63,1044.37 880.63,1019.37 911.63,1019.37 936.93,1044.67 UT55.27@977.03,1044.67
N839997_10857: UT40.27 UT62.7 | length 176.6
  Bottom Layer w7: UT62.7@820.13,634.37 849.63,634.37 876.63,607.37 909.63,607.37 934.93,632.67 UT40.27@975.03,632.67
N839997_11249: UT35.27 UT72.7 | length 183.4
  Bottom Layer w7: UT72.7@815.13,1454.37 853.63,1454.37 880.63,1427.37 908.63,1427.37 935.93,1454.67 UT35.27@976.03,1454.67
N840117: UT50.26 UT70.8 | length 180.6
  Bottom Layer w7: UT70.8@815.13,1841.37 864.27,1841.37 881.27,1824 920.63,1824 931.63,1835.37 931.63,1839.37 940.23,1847.97 UT50.26@976.03,1847.97
N840117_9365: UT60.26 UT68.8 | length 178.5
  Bottom Layer w7: UT68.8@815.13,3076.37 835.63,3076.37 853.63,3058.37 915.63,3058.37 940.23,3082.97 UT60.26@976.03,3082.97
N840117_10477: UT45.26 UT66.8 | length 180.8
  Bottom Layer w7: UT66.8@815.13,2666.37 834.63,2666.37 855.63,2645.37 916.63,2645.37 941.23,2669.97 UT45.26@977.03,2669.97
N840117_10673: UT55.26 UT64.8 | length 182.3
  Bottom Layer w7: UT64.8@815.13,1021.37 844.63,1021.37 862.63,1003.37 919.63,1003.37 932.63,1016.37 932.63,1020.37 941.23,1028.97 UT55.26@977.03,1028.97
N840117_10869: UT40.26 UT62.8 | length 172.1
  Bottom Layer w7: UT62.8@820.13,611.37 840.63,611.37 858.63,593.37 915.63,593.37 939.23,616.97 UT40.26@975.03,616.97
N840117_11261: UT35.26 UT72.8 | length 181.9
  Bottom Layer w7: UT72.8@815.13,1431.37 844.63,1431.37 862.63,1413.37 919.63,1413.37 926.63,1420.37 926.63,1425.37 940.23,1438.97 UT35.26@976.03,1438.97
N840583: UT50.47 UT69.1 | length 167
  Bottom Layer w7: UT69.1@815.13,2180.37 874.63,2180.37 880.63,2186.37 922.63,2186.37 931.33,2177.67 UT50.47@976.03,2177.67
N840583_9368: UT60.47 UT67.1 | length 168.6
  Bottom Layer w7: UT67.1@815.13,3415.37 873.63,3415.37 881.63,3423.37 921.63,3423.37 932.33,3412.67 UT60.47@976.03,3412.67
N840583_10462: UT45.47 UT65.1 | length 168.8
  Bottom Layer w7: UT65.1@815.13,3002.37 861.63,3002.37 868.63,3009.37 925.63,3009.37 935.33,2999.67 UT45.47@977.03,2999.67
N840583_10658: UT55.47 UT63.1 | length 169.2
  Bottom Layer w7: UT63.1@815.13,1360.37 874.63,1360.37 882.63,1368.37 924.63,1368.37 934.33,1358.67 UT55.47@977.03,1358.67
N840583_10854: UT40.47 UT61.1 | length 159.7
  Bottom Layer w7: UT61.1@820.13,950.37 870.63,950.37 874.63,954.37 920.63,954.37 928.33,946.67 UT40.47@975.03,946.67
N840583_11246: UT35.47 UT71.1 | length 168.8
  Bottom Layer w7: UT71.1@815.13,1770.37 876,1770.37 884.63,1779 919.63,1779 929.97,1768.67 UT35.47@976.03,1768.67
N840601: UT50.46 UT69.2 | length 170.6
  Bottom Layer w7: UT69.2@815.13,2157.37 875.63,2157.37 889.63,2171.37 912.63,2171.37 922.03,2161.97 UT50.46@976.03,2161.97
N840601_9374: UT60.46 UT67.2 | length 170.6
  Bottom Layer w7: UT67.2@815.13,3392.37 875.63,3392.37 889.63,3406.37 912.63,3406.37 922.03,3396.97 UT60.46@976.03,3396.97
N840601_10467: UT45.46 UT65.2 | length 171.5
  Bottom Layer w7: UT65.2@815.13,2979.37 816.63,2980.37 877.63,2980.37 890.63,2993.37 913.63,2993.37 923.03,2983.97 UT45.46@977.03,2983.97
N840601_10663: UT55.46 UT63.2 | length 172
  Bottom Layer w7: UT63.2@815.13,1337.37 875.63,1337.37 890.63,1352.37 913.63,1352.37 923.03,1342.97 UT55.46@977.03,1342.97
N840601_10859: UT40.46 UT61.2 | length 164.2
  Bottom Layer w7: UT61.2@820.13,927.37 875.63,927.37 888.63,940.37 911.63,940.37 921.03,930.97 UT40.46@975.03,930.97
N840601_11251: UT35.46 UT71.2 | length 171
  Bottom Layer w7: UT71.2@815.13,1747.37 874.63,1747.37 889.63,1762.37 912.63,1762.37 922.03,1752.97 UT35.46@976.03,1752.97
N840633: UT50.44 UT69.3 | length 171.8
  Bottom Layer w7: UT69.3@815.13,2137.37 824.13,2137.37 872.63,2138.37 889.63,2121.37 918.63,2121.37 927.83,2130.57 UT50.44@976.03,2130.57
N840633_9348: UT60.44 UT67.3 | length 171.3
  Bottom Layer w7: UT67.3@815.13,3372.37 873.63,3372.37 889.63,3356.37 918.63,3356.37 927.83,3365.57 UT60.44@976.03,3365.57
N840633_10466: UT45.44 UT65.3 | length 172.3
  Bottom Layer w7: UT65.3@815.13,2959.37 877.63,2959.37 893.63,2943.37 919.63,2943.37 928.83,2952.57 UT45.44@977.03,2952.57
N840633_10662: UT55.44 UT63.3 | length 171.9
  Bottom Layer w7: UT63.3@815.13,1317.37 875.63,1317.37 890.63,1302.37 919.63,1302.37 928.83,1311.57 UT55.44@977.03,1311.57
N840633_10858: UT40.44 UT61.3 | length 165.8
  Bottom Layer w7: UT61.3@820.13,907.37 871.63,907.37 888.63,890.37 917.63,890.37 926.83,899.57 UT40.44@975.03,899.57
N840633_11250: UT35.44 UT71.3 | length 170.9
  Bottom Layer w7: UT71.3@815.13,1727.37 874.63,1727.37 889.63,1712.37 918.63,1712.37 927.83,1721.57 UT35.44@976.03,1721.57
N840655: UT50.43 UT69.4 | length 170.6
  Bottom Layer w7: UT69.4@815.13,2118.37 824.13,2118.37 868.63,2119.37 882.63,2105.37 927.63,2105.37 937.13,2114.87 UT50.43@976.03,2114.87
N840655_9379: UT60.43 UT67.4 | length 170
  Bottom Layer w7: UT67.4@815.13,3353.37 814.62,3353.37 868.63,3354.37 880.63,3342.37 929.63,3342.37 937.13,3349.87 UT60.43@976.03,3349.87
N840655_10470: UT45.43 UT65.4 | length 169.6
  Bottom Layer w7: UT65.4@815.13,2940.37 876.63,2940.37 887.63,2929.37 930.63,2929.37 938.13,2936.87 UT45.43@977.03,2936.87
N840655_10666: UT55.43 UT63.4 | length 169.1
  Bottom Layer w7: UT63.4@815.13,1298.37 871.63,1298.37 881.63,1288.37 930.63,1288.37 938.13,1295.87 UT55.43@977.03,1295.87
N840655_10862: UT40.43 UT61.4 | length 164.6
  Bottom Layer w7: UT61.4@820.13,888.37 867.63,888.37 881.63,874.37 926.63,874.37 936.13,883.87 UT40.43@975.03,883.87
N840655_11254: UT35.43 UT71.4 | length 169.8
  Bottom Layer w7: UT71.4@815.13,1708.37 870.63,1708.37 882.63,1696.37 927.63,1696.37 937.13,1705.87 UT35.43@976.03,1705.87
N840669: UT50.41 UT69.5 | length 167.1
  Bottom Layer w7: UT69.5@815.13,2098.37 869.63,2098.37 876.63,2091.37 911.63,2091.37 919.53,2083.47 UT50.41@976.03,2083.47
N840669_9375: UT60.41 UT67.5 | length 167.1
  Bottom Layer w7: UT67.5@815.13,3333.37 859.63,3333.37 864.63,3328.37 913.63,3328.37 923.53,3318.47 UT60.41@976.03,3318.47
N840669_10481: UT45.41 UT65.5 | length 168.1
  Bottom Layer w7: UT65.5@815.13,2920.37 862.63,2920.37 867.63,2915.37 925.63,2915.37 935.53,2905.47 UT45.41@977.03,2905.47
N840669_10677: UT55.41 UT63.5 | length 167.7
  Bottom Layer w7: UT63.5@815.13,1278.37 869.63,1278.37 873.63,1274.37 917.63,1274.37 927.53,1264.47 UT55.41@977.03,1264.47
N840669_10873: UT40.41 UT61.5 | length 161.5
  Bottom Layer w7: UT61.5@820.13,868.37 865.63,868.37 873.63,860.37 905.63,860.37 913.53,852.47 UT40.41@975.03,852.47
N840669_11265: UT35.41 UT71.5 | length 166.7
  Bottom Layer w7: UT71.5@815.13,1688.37 869.63,1688.37 875.63,1682.37 914.63,1682.37 922.53,1674.47 UT35.41@976.03,1674.47
N840719: UT60.40 UT67.6 | length 165.3
  Bottom Layer w7: UT67.6@815.13,3313.37 903.63,3313.37 914.23,3302.77 UT60.40@976.03,3302.77
N840719_18000: UT55.40 UT63.6 | length 165.9
  Bottom Layer w7: UT63.6@815.13,1258.37 904.63,1258.37 914.23,1248.77 UT55.40@977.03,1248.77
N840719_18001: UT50.40 UT69.6 | length 165.3
  Bottom Layer w7: UT69.6@815.13,2078.37 862.63,2078.37 863.63,2077.37 900.63,2077.37 910.23,2067.77 UT50.40@976.03,2067.77
N840719_18002: UT45.40 UT65.6 | length 167.1
  Bottom Layer w7: UT65.6@815.13,2900.37 860.63,2900.37 861.63,2901.37 912.63,2901.37 924.23,2889.77 UT45.40@977.03,2889.77
N840719_18003: UT40.40 UT61.6 | length 159.7
  Bottom Layer w7: UT61.6@820.13,848.37 865.63,848.37 867.63,846.37 895.43,846.37 905.03,836.77 UT40.40@975.03,836.77
N840719_18004: UT35.40 UT71.6 | length 164.9
  Bottom Layer w7: UT71.6@815.13,1668.37 908.63,1668.37 918.23,1658.77 UT35.40@976.03,1658.77
N840735: UT50.38 UT69.7 | length 177.9
  Bottom Layer w7: UT69.7@815.13,2059.37 843.63,2059.37 875.63,2027.37 895.63,2027.37 904.63,2036.37 UT50.38@976.03,2036.37
N840735_9360: UT60.38 UT67.7 | length 178.7
  Bottom Layer w7: UT67.7@815.13,3294.37 841.63,3294.37 874.63,3261.37 894.63,3261.37 904.63,3271.37 UT60.38@976.03,3271.37
N840735_10468: UT45.38 UT65.7 | length 178.9
  Bottom Layer w7: UT65.7@815.13,2881.37 844.63,2881.37 876.63,2849.37 896.63,2849.37 905.63,2858.37 UT45.38@977.03,2858.37
N840735_10664: UT55.38 UT63.7 | length 178.5
  Bottom Layer w7: UT63.7@815.13,1239.37 845.63,1239.37 876.63,1208.37 896.63,1208.37 905.63,1217.37 UT55.38@977.03,1217.37
N840735_10860: UT40.38 UT61.7 | length 172.3
  Bottom Layer w7: UT61.7@820.13,829.37 841.63,829.37 874.63,796.37 894.63,796.37 903.63,805.37 UT40.38@975.03,805.37
N840735_11252: UT35.38 UT71.7 | length 177.5
  Bottom Layer w7: UT71.7@815.13,1649.37 844.63,1649.37 875.63,1618.37 895.63,1618.37 904.63,1627.37 UT35.38@976.03,1627.37
N840763: UT50.37 UT69.8 | length 174.3
  Bottom Layer w7: UT69.8@815.13,2036.37 846.63,2036.37 870.63,2012.37 900.63,2012.37 908.93,2020.67 UT50.37@976.03,2020.67
N840763_9393: UT60.37 UT67.8 | length 174.3
  Bottom Layer w7: UT67.8@815.13,3271.37 844.63,3271.37 868.63,3247.37 900.63,3247.37 908.93,3255.67 UT60.37@976.03,3255.67
N840763_10464: UT45.37 UT65.8 | length 174.5
  Bottom Layer w7: UT65.8@815.13,2858.37 842.63,2858.37 865.63,2835.37 902.63,2835.37 909.93,2842.67 UT45.37@977.03,2842.67
N840763_10660: UT55.37 UT63.8 | length 174
  Bottom Layer w7: UT63.8@815.13,1216.37 847.63,1216.37 869.63,1194.37 902.63,1194.37 909.93,1201.67 UT55.37@977.03,1201.67
N840763_10856: UT40.37 UT61.8 | length 167.9
  Bottom Layer w7: UT61.8@820.13,806.37 843.63,806.37 867.63,782.37 900.63,782.37 907.93,789.67 UT40.37@975.03,789.67
N840763_11248: UT35.37 UT71.8 | length 173
  Bottom Layer w7: UT71.8@815.13,1626.37 844.63,1626.37 866.63,1604.37 901.63,1604.37 908.93,1611.67 UT35.37@976.03,1611.67
N840791: UT50.36 UT70.1 | length 169
  Bottom Layer w7: UT70.1@815.13,1985.37 852.63,1985.37 865.63,1998.37 906.63,1998.37 913.23,2004.97 UT50.36@976.03,2004.97
N840791_9372: UT60.36 UT68.1 | length 169
  Bottom Layer w7: UT68.1@815.13,3220.37 843.63,3220.37 856.63,3233.37 908.63,3233.37 915.23,3239.97 UT60.36@976.03,3239.97
N840791_10479: UT45.36 UT66.1 | length 168.8
  Bottom Layer w7: UT66.1@815.13,2810.37 842.63,2810.37 852.63,2820.37 910.63,2820.37 917.23,2826.97 UT45.36@977.03,2826.97
N840791_10675: UT55.36 UT64.1 | length 170.4
  Bottom Layer w7: UT64.1@815.13,1165.37 852.63,1165.37 867.63,1180.37 908.63,1180.37 914.23,1185.97 UT55.36@977.03,1185.97
N840791_10871: UT40.36 UT62.1 | length 162.6
  Bottom Layer w7: UT62.1@820.13,755.37 848.63,755.37 861.63,768.37 906.63,768.37 912.23,773.97 UT40.36@975.03,773.97
N840791_11263: UT35.36 UT72.1 | length 169.4
  Bottom Layer w7: UT72.1@815.13,1575.37 852.63,1575.37 867.63,1590.37 908.63,1590.37 914.23,1595.97 UT35.36@976.03,1595.97
N840803: UT50.35 UT70.2 | length 172
  Bottom Layer w7: UT70.2@815.13,1962.37 858.63,1962.37 880.63,1984.37 914.63,1984.37 919.53,1989.27 UT50.35@976.03,1989.27
N840803_9370: UT60.35 UT68.2 | length 172
  Bottom Layer w7: UT68.2@815.13,3197.37 849.63,3197.37 871.63,3219.37 915.63,3219.37 920.53,3224.27 UT60.35@976.03,3224.27
N840803_10463: UT45.35 UT66.2 | length 171.8
  Bottom Layer w7: UT66.2@815.13,2787.37 848.63,2787.37 867.63,2806.37 916.63,2806.37 921.53,2811.27 UT45.35@977.03,2811.27
N840803_10659: UT55.35 UT64.2 | length 173.5
  Bottom Layer w7: UT64.2@815.13,1142.37 858.63,1142.37 881.63,1165.37 916.63,1165.37 921.53,1170.27 UT55.35@977.03,1170.27
N840803_10855: UT40.35 UT62.2 | length 165.6
  Bottom Layer w7: UT62.2@820.13,732.37 854.63,732.37 876.63,754.37 912.63,754.37 916.53,758.27 UT40.35@975.03,758.27
N840803_11247: UT35.35 UT72.2 | length 172.5
  Bottom Layer w7: UT72.2@815.13,1552.37 858.63,1552.37 882.63,1576.37 916.63,1576.37 920.53,1580.27 UT35.35@976.03,1580.27
N840819: UT50.33 UT70.3 | length 174.4
  Bottom Layer w7: UT70.3@815.13,1942.37 824.13,1942.37 876.63,1943.37 885.63,1934.37 905.63,1934.37 929.13,1957.87 UT50.33@976.03,1957.87
N840819_9349: UT60.33 UT68.3 | length 174.4
  Bottom Layer w7: UT68.3@815.13,3177.37 876.63,3178.37 885.63,3169.37 905.63,3169.37 929.13,3192.87 UT60.33@976.03,3192.87
N840819_10472: UT45.33 UT66.3 | length 176.2
  Bottom Layer w7: UT66.3@815.13,2767.37 869.63,2767.37 880.63,2756.37 906.63,2756.37 930.13,2779.87 UT45.33@977.03,2779.87
N840819_10668: UT55.33 UT64.3 | length 175.4
  Bottom Layer w7: UT64.3@815.13,1122.37 824.13,1122.37 877.63,1124.37 886.63,1115.37 906.63,1115.37 930.13,1138.87 UT55.33@977.03,1138.87
N840819_10864: UT40.33 UT62.3 | length 168.4
  Bottom Layer w7: UT62.3@820.13,712.37 875.63,712.37 884.63,703.37 904.63,703.37 928.13,726.87 UT40.33@975.03,726.87
N840819_11256: UT35.33 UT72.3 | length 173.5
  Bottom Layer w7: UT72.3@815.13,1532.37 878.63,1532.37 885.63,1525.37 905.63,1525.37 929.13,1548.87 UT35.33@976.03,1548.87
N840847: UT50.32 UT70.4 | length 171.2
  Bottom Layer w7: UT70.4@815.13,1923.37 876.63,1923.37 879.63,1920.37 911.63,1920.37 933.43,1942.17 UT50.32@976.03,1942.17
N840847_9342: UT60.32 UT68.4 | length 172
  Bottom Layer w7: UT68.4@815.13,3158.37 869.63,3158.37 873.63,3154.37 910.63,3154.37 933.43,3177.17 UT60.32@976.03,3177.17
N840847_10480: UT45.32 UT66.4 | length 173.4
  Bottom Layer w7: UT66.4@815.13,2748.37 860.63,2748.37 866.63,2742.37 912.63,2742.37 934.43,2764.17 UT45.32@977.03,2764.17
N840847_10676: UT55.32 UT64.4 | length 171.8
  Bottom Layer w7: UT64.4@815.13,1103.37 878.63,1103.37 880.63,1101.37 912.63,1101.37 934.43,1123.17 UT55.32@977.03,1123.17
N840847_10872: UT40.32 UT62.4 | length 165.6
  Bottom Layer w7: UT62.4@820.13,693.37 874.63,693.37 878.63,689.37 910.63,689.37 932.43,711.17 UT40.32@975.03,711.17
N840847_11264: UT35.32 UT72.4 | length 170.8
  Bottom Layer w7: UT72.4@815.13,1513.37 876.63,1513.37 878.63,1511.37 911.63,1511.37 933.43,1533.17 UT35.32@976.03,1533.17
N840871: UT50.30 UT70.5 | length 164
  Bottom Layer w7: UT70.5@815.13,1903.37 914.63,1903.37 922.03,1910.77 UT50.30@976.03,1910.77
N840871_9343: UT60.30 UT68.5 | length 164
  Bottom Layer w7: UT68.5@815.13,3138.37 914.63,3138.37 922.03,3145.77 UT60.30@976.03,3145.77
